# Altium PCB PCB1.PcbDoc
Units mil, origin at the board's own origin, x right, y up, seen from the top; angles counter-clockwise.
Board outline 1580.83 x 3352.49 mil, 2 copper layers (Top Layer, Bottom Layer); 29 components, 18 nets, 113 pads, 12 vias.
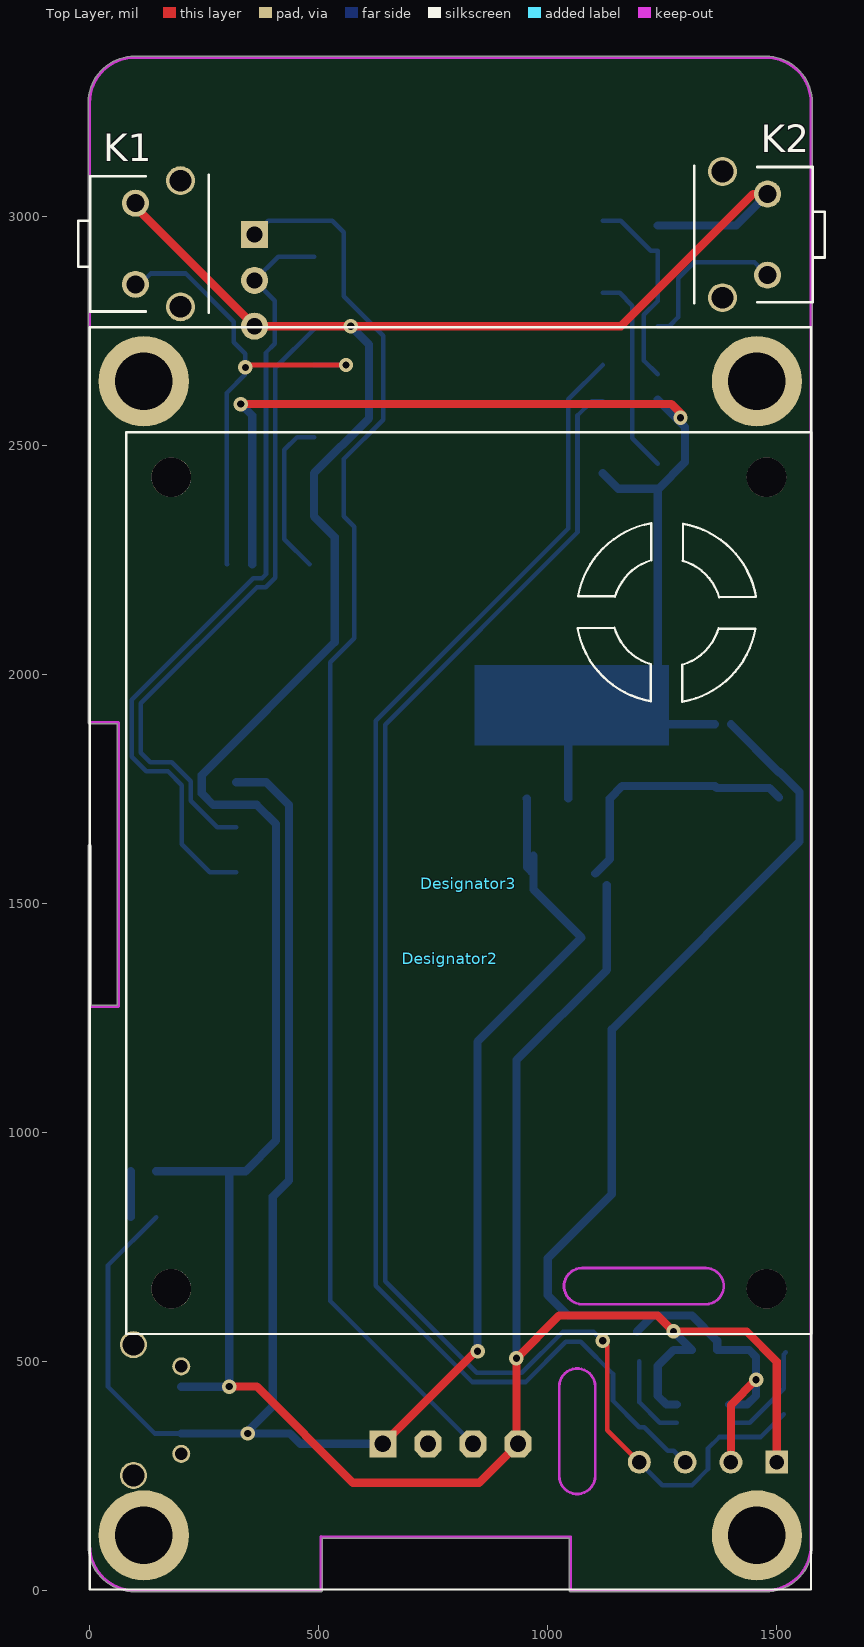
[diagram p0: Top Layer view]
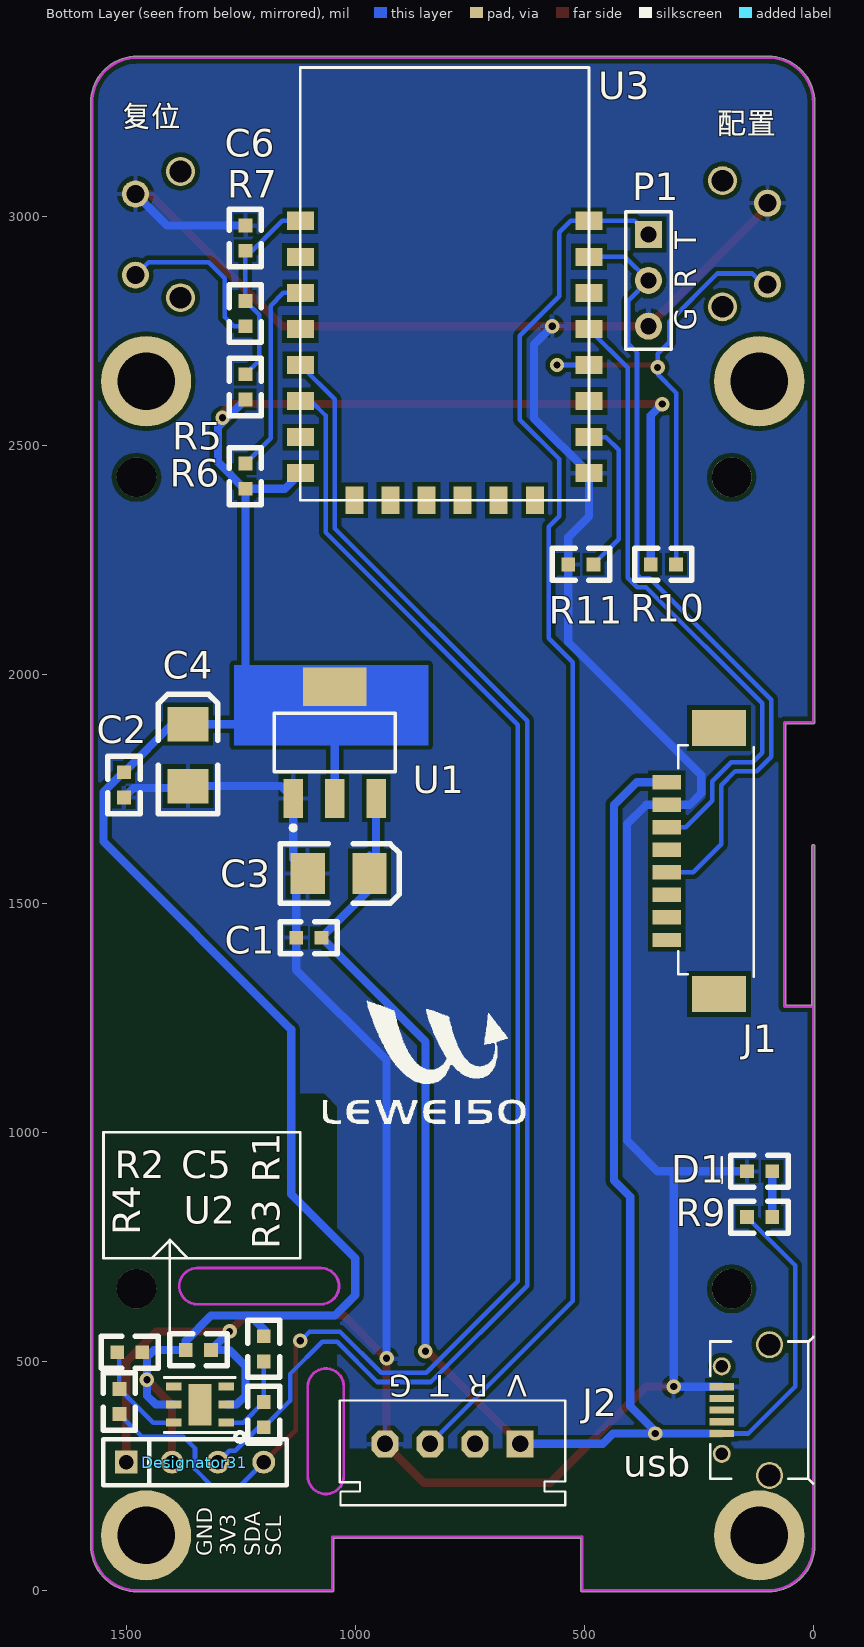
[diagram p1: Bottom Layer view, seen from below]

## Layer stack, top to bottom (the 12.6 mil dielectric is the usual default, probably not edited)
Top Layer: signal copper 1.4
Dielectric: dielectric 12.6, FR-4, Dk 4.8
Bottom Layer: signal copper 1.4

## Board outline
-3.01,98.43 -3.01,1625 cw(c0,1625) 3.01,1625 3.01,1278.01 59.98,1278.01 59.98,1891.99 0,1891.99 cw(c0,1895) -3.01,1895 -3.01,3248.03 cw(c98.43,3248.03) 98.43,3349.47 1476.38,3349.47 cw(c1476.38,3248.03) 1577.82,3248.03 1577.82,98.43 cw(c1476.38,98.43) 1476.38,-3.01 1050,-3.01 cw(c1050,0) 1046.98,0 1046.98,114.35 508.02,114.35 508.02,0 cw(c505,0) 505,-3.01 98.43,-3.01 cw(c98.43,98.43)

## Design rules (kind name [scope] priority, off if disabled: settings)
Clearance [All] p1: gap=10
ComponentClearance [All] p1 off: gap=10 collisioncheckmode=3 verticalgap=10 showdistances=FALSE
PolygonConnect [All] p1: connectstyle=Relief reliefconductorwidth=10 reliefentries=4 polygonreliefangle="90 Angle"
RoutingVias [All] p1: holewidth=28 width=50 viastyle="Through Hole" minholewidth=28 minwidth=50 maxholewidth=28 maxwidth=50
SilkToSilkClearance [All] p1 off: silktosilkclearance=10
SilkscreenOverComponentPads [All] p1 off: minsilkscreentomaskgap=10
SolderMaskExpansion [All] p1: expansion=4
TestPointUsage [All] p1: valid=0 allowmultiple=FALSE
Testpoint [All] p1: side=15 testpointundercomponent=TRUE minsize=40 maxsize=100 preferedsize=60 minholesize=0 maxholesize=40 preferedholesize=32 testpointgrid=1 style=1023 order=0-112345678
Width [All] p1: maxlimit=30 minlimit=10 preferedwidth=10
21 further rules are at their usual default settings.

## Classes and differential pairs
component class Sheet1: C1 C2 C3 C4 C5 C6 D1 J1 J2 K1 K2 P1 R1 R2 R3 R4 R5 R6 R7 R9 R10 R11 U1 U2 U3 usb

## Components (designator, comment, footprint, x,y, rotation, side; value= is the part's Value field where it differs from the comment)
C1 "0.1uf" 0603 1128.98,1425 r180 bottom
C2 "0.1uf" 0603 1505,1731.02 r90 bottom
C3 "10uf/16V" 3528 968.98,1565 r180 bottom
C4 "10uf/16V" 3528 1365,1891.02 r90 bottom
C5 "0.1uf" 0603 1315,525 r0 bottom
C6 "0.1uf" 0603 1240,2980 r270 bottom
D1 "LED2" 0603 90,915 r0 bottom
Designator2 "Comment" LCD 787.4,1380 r180 top
Designator3 "Comment" PM2.5 80,560 r0 top
Designator31 "Comment" SIP4 1500,280 r180 bottom
J1 "DIP-1X08" 1.27*8 320,1420 r90 bottom (schematic designator J4)
J2 "DIP-1X04" XH-1X04-2.5 640,320 r0 bottom (schematic designator J3)
K1 "FLASH" upkey 100,2940 r90 top
K2 "RST" upkey 1480,2960 r270 top
P1 "Header 3" HDR1X3 360,2960 r270 bottom
R1 "10K" 0603 1200,500 r90 bottom
R2 "10K" 0603 1520,520 r180 bottom
R3 "100" 0603 1200,411.26 r270 bottom
R4 "100" 0603 1515,440 r270 bottom
R5 "10K" 0603 1240,2600 r90 bottom
R6 "10K" 0603 1240,2460 r270 bottom
R7 "470" 0603 1240,2760 r90 bottom
R9 "470" 0603 90,815 r0 bottom
R10 "10K" 0603 300,2240 r0 bottom
R11 "10K" 0603 480,2240 r0 bottom
U1 "LM1117_3.3" SOT223 1045,1851.02 r180 bottom
U2 "SI7021" si7021 1282,445 r0 bottom
U3 "ESP-12M" wifi 1120,2380 r180 bottom
usb "Header 5" MICROUSB 200,393.7 r270 bottom

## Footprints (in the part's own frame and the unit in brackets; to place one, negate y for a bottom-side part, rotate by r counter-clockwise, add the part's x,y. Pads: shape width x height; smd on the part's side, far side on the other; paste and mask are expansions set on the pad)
1.27*8 [mm]
  rect 0.8x1.6 smd: 1(8.75,0) 2(7.5,0) 3(6.25,0) 4(5,0) 5(3.75,0) 6(2.5,0) 7(1.25,0) 8(0,0)
  rect 2x3 smd: ""(-3,-2.9) ""(11.75,-2.9)
  silkscreen extent -2.03,-4.83 10.79,-0.63
0603 [mil]
  rect 30x30 smd: 1(0,0) 2(55,0)
  silkscreen extent -35,-35 90,35
3528 [mil]
  rect 75x90 smd: 1(0,0) 2(-135,0)
  silkscreen extent -195,-65 65,65
HDR1X3 [mm] "Connector; Header; 3 Position"
  rect 1.5x1.5 hole 0.9: 1(0,0)
  round 1.5 hole 0.9: 2(2.54,0) 3(5.08,0)
  silkscreen extent -1.27,-1.27 6.35,1.27
LCD [mm]
  round 5 hole 3.2: ""(-17,32) ""(-17,-32) ""(17,32) ""(17,-32)
  silkscreen extent -20,-35 20,35
MICROUSB [mm]
  rect 0.4x1.35 smd: 1(1.3,0) 2(0.65,0) 3(0,0) 4(-0.65,0) 5(-1.3,0)
  round 1.5 hole 1.2: ""(-3.625,2.65) ""(3.625,2.65)
  round 1 hole 0.7: ""(-2.425,0) ""(2.425,0)
  silkscreen extent -4.06,-0.64 4.06,5.08
PM2.5 [mm]
  round 2.2 hole 2.2: ""(2.5,2.5) ""(2.5,47.5) ""(35.5,2.5) ""(35.5,47.5)
  silkscreen extent 0,0 38,50
si7021 [mm]
  rect 0.85x0.45 smd: 1(0,2) 2(0,1) 3(0,0) 4(2.9,0) 5(2.9,1) 6(2.9,2)
  rect 1.3x2.3 smd: ""(1.45,1)
  silkscreen extent -1.02,-0.51 3.43,3.05
SIP4 [mil]
  rect 50x50 hole 32: 1(0,0)
  round 50 hole 32: 2(100,0) 3(200,0) 4(300,0)
  silkscreen extent -50,-50 350,50
SOT223 [mm] "SOT-223/SC-73; 4 Leads; Body 6.7 x 7.3 mm, inc. leads (LxW max)"
  rect 1.1x2.15 smd: 1(-2.3,-3.1) 2(0,-3.1) 3(2.3,-3.1)
  rect 3.5x2.15 smd: 4(0,3.1)
  silkscreen extent -3.35,-4.85 3.35,1.63
upkey [mm]
  round 1.5 hole 1: 1(-2.25,0) 2(2.25,0)
  round 1.6 hole 1.2: ""(-3.5,-2.5) ""(3.5,-2.5)
  silkscreen extent -3.81,-4.06 3.81,3.17
wifi [mm]
  rect 1.5x1 smd: 1(0,15.5) 2(0,13.5) 3(0,11.5) 4(0,9.5) 5(0,7.5) 6(0,5.5) 7(0,3.5) 8(0,1.5) 15(16,1.5) 16(16,3.5) 17(16.002,5.5) 18(16.002,7.5) 19(16.002,9.5) 20(16.002,11.5) 21(16.002,13.5) 22(16,15.5)
  rect 1x1.5 smd: 9(3,0) 10(5,0) 11(7,0) 12(9,0) 13(11,0) 14(13,0)
  silkscreen extent 0,0 16,24
XH-1X04-2.5 [mm]
  rect 1.5x1.5 hole 0.9: 1(0,0)
  oct 1.5x1.5 hole 0.9: 2(2.5,0) 3(5,0) 4(7.5,0)
  silkscreen extent -2.5,-2.4 10,3.4

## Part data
C1 C2 C5 C6: library part "Cap Semi", "Capacitor (Semiconductor SIM Model)"
C3 C4: library part "Cap Pol3", "Polarized Capacitor (Surface Mount)"
D1: "Typical RED, GREEN, YELLOW, AMBER GaAs LED"
J1: "Header, 8-Pin"
J2: "Header, 4-Pin"
K1 K2: library part SW
P1: "Header, 3-Pin"
R1 R2 R3 R4 R5 R6 R7 R9 R10 R11: library part Res3, "Resistor"
U1: library part LM1117
usb: "Header, 5-Pin"

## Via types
v1: diameter 31.5, hole 15.75, Top Layer to Bottom Layer, 12 vias

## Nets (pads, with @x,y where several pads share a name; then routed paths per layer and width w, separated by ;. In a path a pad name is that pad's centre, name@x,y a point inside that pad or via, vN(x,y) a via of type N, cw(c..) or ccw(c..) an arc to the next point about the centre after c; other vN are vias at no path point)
3V3: C2.2 C4.1 C5.2 Designator31.2 R1.2 R2.2 R5.1 R6.2 R10.2 U1.2 U1.4 U2.5 U3.8 | length 5107.1
  Top Layer w18: v1(330,2590) 1270,2590 v1@1295,2565 ; Designator31.2 1400,405 v1(1455,460)
  Bottom Layer w18: v1(330,2590) 355,2565 R10.2 ; U1.2 U1.4 1145.18,1973.07 ; U3.8 1154.06,2405 R6.2 ; 1193.98,1891.02 C4.1 ; R1.2@1195,565 1230.17,600.17 ; 1235,1995 1240,2000 R6.2 ; R5.1 1300,2540 1300,2463.13 1241.87,2405 R6.2 ; U2.5 1435.63,405.63 1455,425 1455,465 1455,510 1440,525 C5.2 1370,545 1314.83,600.17 1230.17,600.17 ; C4.1@1400,1891.02 C2.2 1506.87,1786.02 1550,1742.89 1550,1635 1140,1225 1140,865 1000,725 1000,645 1044.83,600.17 1230.17,600.17
  other v1: 1290,2560
5V: C1.2 C3.1 J1.1 J2.1 R9.2 U1.3 usb.1 | length 4299.8
  Top Layer w18: J2.1 841.97,521.97 v1(846.97,521.97)
  Bottom Layer w10: R9.2 40,710 40,445 142.48,342.52 usb.1
  Bottom Layer w18: usb.1 v1@340,342.52 ; J1.1 385.51,1764.49 435,1715 435,895 400,860 400,402.52 v1@340,342.52 ; J2.1 460,320 437.48,342.52 v1(345,342.52) v1@340,342.52 ; v1(846.97,521.97) 846.97,1197.99 C1.2 968.98,1530 C3.1 ; U1.3 955,1728.43 955,1578.98 C3.1 ; C3.1@963.98,1570 C3.1 ; C3.1@968.98,1603.98 C3.1
D+: usb.3
D-: usb.2
GND: C1.1 C2.1 C3.2 C4.2 C5.1 C6.1 D1.2 Designator31.1 J1.2 J2.4 K1.2 K2.1 P1.3 R11.2 U1.1 U2.2 U3.15 usb.5 | length 8648.8
  Top Layer w18: K1.2 100,3020 P1.3 v1(570,2760) 1160,2760 1448.58,3048.58 K2.1 ; v1(305,445) 365,445 575,235 850.28,235 J2.4 J2.4@931.76,323.52 ; J2.4@931.76,343.24 v1(931.76,506.76) ; v1@935.42,510.42 v1(931.76,506.76) ; 1170,600 1160,600 ; Designator31.1 1500,500 1434.58,565.42 v1(1274.58,565.42) 1240,600 1160,600 ; v1(931.76,506.76) 1025,600 1160,600
  Bottom Layer w18: D1.2 275,915 ; usb.5 304.88,444.88 v1(305,445) 305,915 ; 285,915 275,915 ; v1(570,2760) 610,2720 610,2645 ; 610,2680 610,2645 ; v1(931.76,506.76) 931.76,1157.78 1128.98,1355 C1.1 C3.2@1128.98,1540 ; C3.2 1135.55,1596.57 U1.1 1162.6,1756.02 C4.2 1369,1752.02 1484,1752.02 C2.1 ; C6.1 1411.42,2980 K2.1 ; v1(1274.58,565.42) C5.1 1275,525 1240,490 1240,425 1259.37,405.63 U2.2 ; 275,915 305,915 ; 305,915 340,915 407,982 407,1673 364.72,1715.28 J1.2 269.72,1715.28 245,1740 245,1780 535,2070 R11.2 535,2300 490.08,2344.92 U3.15 610,2558.98 610,2645
GPIO4: J1.3 U3.19 | length 1393.7
  Bottom Layer w10: J1.3 278.94,1666.06 221,1724 221,1749.94 221,1766.51 179.28,1808.23 132.27,1808.23 111.77,1828.73 111.77,1936.47 365.31,2190 384.5,2190 405,2210.5 405,2669.02 U3.19
GPIO12: Designator31.4 R4.2 U3.6 | length 3459.8
  Top Layer w10: v1(1120,545) 1130,535 1130,350 Designator31.4
  Bottom Layer w10: v1(1120,545) 1100,565 1033.48,565 943.48,475 845,475 645,675 645,1890 1065,2310 1065,2565 1096.54,2596.54 U3.6 ; Designator31.4 1250,230 1315,230 1350,265 1350,310 1375,335 1465,335 R4.2
GPIO14: Designator31.3 R3.2 U3.5 | length 3156.7
  Bottom Layer w10: U3.5 1045,2600.28 1045,2318.28 625,1898.28 625,665 835,455 951.77,455 1039.27,542.51 1072.49,542.51 1142.5,472.5 1142.5,413.76 R3.2 1210.46,356.26 1261.72,305 1275,305 Designator31.3
NetC6_2: C6.2 R5.2 R7.2 U3.1 | length 441.9
  Bottom Layer w10: U3.1 1159.76,2990.24 1225,2925 C6.2 R7.2 1210,2785 1210,2685 R5.2
NetD1_1: D1.1 R9.1 | length 100
  Bottom Layer w18: R9.1 D1.1
NetK1_1: K1.1 R10.1 U3.18 | length 1115.3
  Top Layer w10: v1@340,2675.28 v1(559.72,2675.28)
  Bottom Layer w10: K1.1 110,2851.42 133.58,2875 210,2875 315,2770 315,2725 340,2700 340,2655 299.25,2614.25 299.25,2240.75 R10.1 ; U3.18 v1(559.72,2675.28)
  other v1: 340,2670
NetK2_2: K2.2 R7.1 | length 359.6
  Bottom Layer w10: R7.1 1265,2760 1285,2780 1285,2865 1320,2900 1451.42,2900 K2.2
NetR1_1: R1.1 R3.1 U2.1 | length 189.4
  Bottom Layer w10: R1.1 R3.1 1245,366.26 U2.1
NetR2_1: R2.1 R4.1 U2.6 | length 233.2
  Bottom Layer w10: U2.6@1397.43,365 U2.6 1441.26,366.26 R4.1 1515,515 R2.1
NetR6_1: R6.1 U3.3 | length 444.3
  Bottom Layer w10: U3.3 1157.24,2832.76 1185,2805 1185,2515 R6.1
NetR11_1: R11.1 U3.16 | length 349.4
  Bottom Layer w10: R11.1 425,2295 425,2490 452.8,2517.8 U3.16
RXD0: J1.5 P1.2 U3.21 | length 1758.8
  Bottom Layer w10: J1.5 262.36,1567.64 201,1629 201,1758.23 171,1788.23 123.99,1788.23 91.77,1820.45 91.77,1944.75 357.02,2210 376.21,2210 385,2218.79 385,2702.5 404.53,2722.03 404.53,2815.47 P1.2 411.5,2911.5 U3.21
TXD0: J2.3 P1.1 U3.22 | length 3094.2
  Bottom Layer w10: P1.1 390.24,2990.24 U3.22 529.76,2990.24 555,2965 555,2825 640.75,2739.25 640.75,2555.78 555,2470.04 555,2345 577.42,2322.58 577.42,2078.48 525,2026.06 525,631.85 J2.3
pads on no net: Designator2. Designator3. J1. J1.4 J1.6 J1.7 J1.8 J2.2 K1. K2. U2. U2.3 U2.4 U3.2 U3.4 U3.7 U3.9 U3.10 U3.11 U3.12 U3.13 U3.14 U3.17 U3.20 usb. usb.4

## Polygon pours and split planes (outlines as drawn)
GND on Bottom Layer "BottomLayer-No Net" (solid, remove dead copper, pour order 1000): -116.04,3375.75 1693.96,3375.75 1798.96,3270.75 1793.96,3265.75 1793.96,1085.75 1068.96,1085.75 1063.96,1080.75 1038.96,1055.75 1038.96,310.75 -151.04,310.75 -181.04,280.75

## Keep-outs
Keep-Out Layer:
  lines w6: 0,1275 62.99,1275 62.99,1895 0,1895 0,3248.03 cw(c98.43,3248.03) 98.43,3346.46 1023.62,3346.46 1476.38,3346.46 cw(c1476.38,3248.03) 1574.8,3248.03 1574.8,98.43 cw(c1476.38,98.43) 1476.38,0 1050,0 1050,117.36 505.2,117.36 ; 0,1625 0,98.43 ccw(c98.43,98.43) 98.43,0 505,0 505,117.56 ; 1025,250 ccw(c1064.37,250) 1103.74,250 1103.74,445 ccw(c1064.37,445) 1025,445 1025,250 ; 1075,625 cw(c1075,664.37) 1075,703.74 1345,703.74 cw(c1345,664.37) 1345,625 1075,625

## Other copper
Bottom Layer:
  region net 3V3: 840,2020 840,1845 1265,1845 1265,2020

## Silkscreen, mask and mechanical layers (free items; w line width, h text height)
Bottom Overlay:
  drawing of 991 lines, arcs and shapes, not listed
  text "复位" at 1510,3180 h80
  text "配置" at 210,3165 h80
  text "G  R  T" at 240,2750 h80 r270
  text "V  R  T  G" at 625,485 h80 r180
  text "SCL" at 1150,75 h59.06 r270
  text "SDA" at 1195,75 h59.06 r270
  text "3V3" at 1248.67,75.45 h59.06 r270
  text "GND" at 1300,75 h59.06 r270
